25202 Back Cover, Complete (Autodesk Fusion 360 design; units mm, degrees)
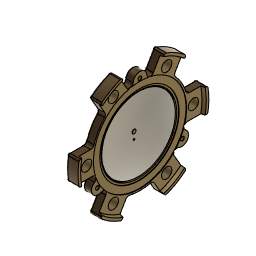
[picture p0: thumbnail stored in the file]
parameter "Diaphragm_Slot_Depth" = 0.508 comment "SWG 25"
parameter "Diaphragm_Tolerance" = 0.0992 (= "( 1 / 256 ) * 1 in")
parameter "Bolt_Holes_Tolerance" = 1.5875 (= "( 1 / 16 ) * 1 in")
parameter "Diaphragm_Ring_Slot_Depth" = 0.508 comment "SWG 25"
sketch "Main Profile" plane through (0, 0, 0) normal (0, 1, 0) x axis (1, 0, 0)
  line L1 (0, 42.8625) -> (0, -42.8625)
  line L2 (0, -44.45) -> (0, -42.8625)
  line L3 (114.3635, -44.45) -> (0, -44.45)
  line L4 (0, -50.8) -> (0, -44.45)
  line L5 (-25.4, 0) -> (0, 0)
  line L6 (17.4625, 0) -> (0, 0)
  line L7 (-7.9375, -44.45) -> (0, -44.45)
  line L8 (-7.9375, -34.5258) -> (-7.9375, -44.45)
  line L9 (-0.508, -42.8625) -> (0, -42.8625)
  line L10 (-0.508, -36.5125) -> (-0.508, -42.8625)
  line L11 (-1.016, -36.5125) -> (-0.508, -36.5125)
  line L12 (-1.016, -34.925) -> (-1.016, -36.5125)
  line L13 (-2.6035, -34.925) -> (-1.016, -34.925)
  line L14 (-2.6035, -32.3877) -> (-2.6035, -34.925)
  line L15 (-7.9375, -50.8) -> (0, -50.8)
  line L16 (-7.9375, -44.45) -> (-7.9375, -50.8)
  line L17 (-25.4, 0) -> (-20.6375, 0)
  line L18 (-6.35, 0) -> (-20.6375, 0)
  line L19 (-6.35, -1.5875) -> (-6.35, 0)
  line L20 (-6.35, -4.7625) -> (-6.35, -1.5875)
  line L21 (-25.3706, -1.5875) -> (-6.35, -1.5875)
  line L22 (-20.1046, -6.35) -> (-6.35, -4.7625)
  line L23 (-1.3921, -33.9302) -> (-2.16, -34.1313)
  line L24 (122.1287, -1.5875) -> (-1.3921, -33.9302)
  line L25 (-5.5562, 0) -> (-5.5562, -1.5875)
  line L26 (-5.5562, 0) -> (-6.35, 0)
  line L27 (-5.5562, -1.5875) -> (-6.35, -1.5875)
  line L28 (-4.7625, 0) -> (-5.5562, 0)
  line L29 (-19.05, -2.3812) -> (-19.05, -1.5875)
  line L30 (-25.3338, -2.3812) -> (-19.05, -2.3812)
  line L31 (-19.05, -6.2283) -> (-19.05, -2.3812)
  line L32 (-5.5561, -1.7859) -> (-5.4569, -1.7859)
  arc A1 centre (17.4625, 0) radius 42.8625 clockwise from (-7.9375, -34.5258) to (-25.4, 0)
  arc A2 centre (17.4625, 0) radius 38.1 clockwise from (-2.6035, -32.3877) to (-20.6375, 0)
  arc A3 centre (-16.2556, -9.1018) radius 3.175 clockwise from (-19.3209, -9.9293) to (-16.6197, -5.9478)
  arc A4 centre (122.1287, -1.5875) radius 128.4787 clockwise from (-2.16, -34.1313) to (-6.35, -1.5875)
  arc A5 centre (122.1287, -1.5875) radius 127.685 clockwise from (-1.3921, -33.9302) to (-5.5562, -1.5875)
  arc A6 centre (-7.4064, 0) radius 2.6439 clockwise from (-4.7625, 0) to (-5.4569, -1.7859)
  arc A7 centre (-46.7072, 0) radius 21.5057 clockwise from (-25.2016, 0) to (-25.3338, -2.3812)
  point P4 (0, 0)
  point P1 (0, 0)
  point P8 (0, 0)
  point P12 (0, 0)
  point P11 (17.4625, 0)
  point P13 (17.4625, 0)
  point P22 (-20.6375, 0)
  point P24 (-6.35, 0)
  point P27 (-25.3706, -1.5875)
  point P28 (-20.1046, -6.35)
  point P30 (-16.6197, -5.9478)
  point P29 (-19.3209, -9.9293)
  point P20 (-2.6035, -32.3877)
  point P33 (122.1287, -1.5875)
  point P35 (122.1287, -1.5875)
  point P38 (-5.5562, 0)
  point P39 (-4.7625, 0)
  point P40 (-19.05, -1.5875)
  point P42 (-25.3338, -2.3812)
  point P43 (-19.05, -6.2283)
  point P45 (-7.4064, 0)
  point P46 (-5.5561, -1.7859)
  point P47 (-25.2016, 0)
  point P48 (-46.7072, 0)
  point P5 (0, -44.45)
  point P2 (0, -42.8625)
  point P7 (0, -50.8)
  point P9 (-25.4, 0)
  point P14 (-7.9375, -44.45)
  point P15 (-0.508, -42.8625)
  point P16 (-0.508, -36.5125)
  point P17 (-1.016, -36.5125)
  point P18 (-1.016, -34.925)
  point P26 (-6.35, -4.7625)
  point P32 (-2.16, -34.1313)
  point P34 (-1.3921, -33.9302)
  point P44 (-5.4569, -1.7859)
  vertical L1
  midpoint L1 P4
  coincident P1 P4
  parallel L1 L2
  horizontal L3
  perpendicular L3 L4
  coincident P4 P8
  horizontal L5
  coincident P4 P12
  coincident P11 P13
  horizontal L6
  horizontal L7
  vertical L8
  perpendicular L1 L9
  perpendicular L9 L10
  perpendicular L10 L11
  perpendicular L11 L12
  perpendicular L12 L13
  perpendicular L13 L14
  perpendicular L4 L15
  vertical L16
  coincident L5 P22
  concentric A1 A2
  coincident L5 P24
  perpendicular L5 L19
  perpendicular L5 L20
  coincident A1 P27
  horizontal L21
  coincident A2 P28
  tangent L22 A3
  coincident L22 P30
  coincident A2 P29
  tangent A2 A3
  tangent L20 A4
  coincident P20 A4
  coincident P33 P35
  parallel L23 L24
  concentric A4 A5
  coincident L5 P38
  tangent A5 L25
  vertical L25
  coincident L5 P39
  perpendicular L25 L28
  coincident L21 P40
  perpendicular L21 L29
  coincident A1 P42
  perpendicular L29 L30
  coincident L22 P43
  perpendicular L30 L31
  coincident L5 P45
  coincident A5 P46
  horizontal L32
  coincident L5 P47
  coincident L17 P48
  dimension "d1" distance P1 P5 = 44.45 (= "1 3/4")
  dimension "d2" distance P2 P5 = 1.5875 (= "( 1 / 16 ) * 1 in")
  dimension "d4" distance P4 P7 = 50.8
  dimension "d6" radius A1 = 42.8625 (= "1 11/16")
  dimension "d7" distance P8 P9 = 25.4
  dimension "d8" distance P5 P14 = 7.9375 (= "( 5 / 16 ) * 1 in")
  dimension "d10" distance P2 P15 = 0.508 (= "Diaphragm_Ring_Slot_Depth")
  dimension "d11" distance P16 P17 = 0.508 (= "Diaphragm_Slot_Depth")
  dimension "d12" distance P15 P16 = 6.35 (= "( 1 / 4 ) * 1 in")
  dimension "d13" distance P17 P18 = 1.5875 (= "( 1 / 16 ) * 1 in")
  dimension "d14" distance A1 A2 = 4.7625 (= "( 3 / 16 ) * 1 in")
  dimension "d16" distance L18 L21 = 1.5875 (= "( 1 / 16 ) * 1 in")
  dimension "d17" distance L5 P26 = 4.7625 (= "( 3 / 16 ) * 1 in")
  dimension "d18" distance L5 P28 = 6.35 (= "( 1 / 4 ) * 1 in")
  dimension "d19" radius A3 = 3.175 (= "( 1 / 8 ) * 1 in")
  dimension "d20" distance P9 L20 = 19.05 (= "( 3 / 4 ) * 1 in")
  dimension "d56" distance P32 P34 = 0.7937 (= "( 1 / 32 ) * 1 in")
  dimension "d58" distance L6 P32 = 34.1313 (= "1 11/32")
  dimension "d67" distance P38 P39 = 0.7937 (= "( 1 / 32 ) * 1 in")
  dimension "d77" distance P9 L31 = 6.35 (= "( 1 / 4 ) * 1 in")
  dimension "d79" distance L5 L30 = 2.3813 (= "( 3 / 32 ) * 1 in")
  dimension "d80" distance P44 P46 = 0.0992 (= "( 1 / 256 ) * 1 in")
  dimension "d82" distance L27 L32 = 0.1984 (= "( 1 / 128 ) * 1 in")
  dimension "d83" distance P9 P47 = 0.1984 (= "( 1 / 128 ) * 1 in")
  dimension "d84" distance L12 L14 = 1.5875
  dimension "d3" Text1-Height = 6.35 (= "( 1 / 4 ) * 1 in")
  dimension "d5" Text2-Height = 6.35
revolve "Revolve1" sketch "Main Profile" AlongAngle 360
sketch "Flange Profile" plane through (0, 0, 0) normal (1, 0, 0) x axis (0, 1, 0)
  line L1 (0, 50.8) -> (0, 0)
  line L2 (60.325, 0) -> (0, 0)
  line L3 (60.325, -11.1125) -> (60.325, 11.1125)
  line L4 (43.0385, 11.1125) -> (60.325, 11.1125)
  line L5 (43.0385, -11.1125) -> (60.325, -11.1125)
  line L6 (39.7862, 46.6867) -> (20.5388, 57.7992)
  line L7 (11.8956, 42.8287) -> (20.5388, 57.7992)
  line L8 (31.143, 31.7162) -> (39.7862, 46.6867)
  line L9 (30.1625, 52.243) -> (0, 0)
  line L10 (-20.5388, 57.7992) -> (-39.7862, 46.6867)
  line L11 (-31.143, 31.7162) -> (-39.7862, 46.6867)
  line L12 (-11.8956, 42.8287) -> (-20.5388, 57.7992)
  line L13 (-30.1625, 52.243) -> (0, 0)
  line L14 (-60.325, 11.1125) -> (-60.325, -11.1125)
  line L15 (-43.0385, -11.1125) -> (-60.325, -11.1125)
  line L16 (-43.0385, 11.1125) -> (-60.325, 11.1125)
  line L17 (-60.325, 0) -> (0, 0)
  line L18 (-39.7862, -46.6867) -> (-20.5388, -57.7992)
  line L19 (-11.8956, -42.8287) -> (-20.5388, -57.7992)
  line L20 (-31.143, -31.7162) -> (-39.7862, -46.6867)
  line L21 (-30.1625, -52.243) -> (0, 0)
  line L22 (20.5388, -57.7992) -> (39.7862, -46.6867)
  line L23 (31.143, -31.7162) -> (39.7862, -46.6867)
  line L24 (11.8956, -42.8287) -> (20.5388, -57.7992)
  line L25 (30.1625, -52.243) -> (0, 0)
  line L26 (-43.9941, -25.4) -> (0, 0)
  line L27 (43.9941, -25.4) -> (0, 0)
  circle C1 centre (0, 0) radius 42.8625
  circle C2 centre (0, 0) radius 44.45
  circle C3 centre (0, 45.2437) radius 1.5875
  arc A1 centre (0, 44.45) radius 6.35 clockwise from (-6.3375, 44.8477) to (6.3375, 44.8477)
  circle C4 centre (0, 0) radius 32.3877
  circle C5 centre (0, 0) radius 34.925
  circle C6 centre (0, 0) radius 34.925
  circle C7 centre (0, 0) radius 36.5125
  circle C8 centre (0, 0) radius 36.5125
  circle C9 centre (0, 0) radius 42.8625
  circle C10 centre (49.2125, 0) radius 4.7625
  circle C11 centre (0, 0) radius 60.325
  circle C12 centre (0, 0) radius 57.15
  circle C13 centre (24.6063, 42.6193) radius 4.7625
  circle C14 centre (-24.6062, 42.6193) radius 4.7625
  circle C15 centre (-49.2125, 0) radius 4.7625
  circle C16 centre (-24.6063, -42.6193) radius 4.7625
  circle C17 centre (24.6062, -42.6193) radius 4.7625
  arc A2 centre (9.508, 45.0467) radius 3.1767 clockwise from (12.2591, 43.4584) to (6.3375, 44.8477)
  arc A3 centre (-9.508, 45.0467) radius 3.1767 clockwise from (-6.3375, 44.8477) to (-12.2591, 43.4584)
  arc A4 centre (-34.2576, -30.7575) radius 3.1767 clockwise from (-35.6705, -27.9123) to (-31.5065, -32.3459)
  arc A5 centre (-38.4948, -22.225) radius 6.35 clockwise from (-35.6705, -27.9123) to (-42.008, -16.9354)
  arc A6 centre (-43.7656, -14.2892) radius 3.1767 clockwise from (-43.7656, -11.1125) to (-42.008, -16.9354)
  circle C18 centre (-39.1822, -22.6219) radius 1.5875
  arc A7 centre (43.7656, -14.2892) radius 3.1767 clockwise from (42.008, -16.9354) to (43.7656, -11.1125)
  arc A8 centre (38.4948, -22.225) radius 6.35 clockwise from (42.008, -16.9354) to (35.6705, -27.9123)
  arc A9 centre (34.2576, -30.7575) radius 3.1767 clockwise from (31.5065, -32.3459) to (35.6705, -27.9123)
  circle C19 centre (39.1822, -22.6219) radius 1.5875
  point P1 (0, 0)
  point P3 (0, 0)
  point P4 (0, 50.8)
  point P9 (0, 44.45)
  point P10 (0, 0)
  point P14 (60.325, 0)
  point P11 (60.325, 0)
  point P18 (43.0385, 11.1125)
  point P19 (43.0385, -11.1125)
  point P20 (49.2125, 0)
  point P58 (12.2591, 43.4584)
  point P60 (-12.2591, 43.4584)
  point P6 (0, 45.2437)
  point P12 (60.325, 11.1125)
  point P13 (60.325, -11.1125)
  point P28 (0, 0)
  coincident P1 P3
  vertical L1
  coincident P4 A1
  coincident L1 P9
  coincident P1 P10
  perpendicular L1 L2
  vertical L3
  midpoint L3 P14
  coincident P11 P14
  coincident C2 P18
  perpendicular L3 L4
  coincident C2 P19
  perpendicular L3 L5
  coincident L2 P20
  concentric C4 C11
  coincident P14 C11
  concentric C6 C12
  coincident L7 P58
  tangent A1 A2
  tangent L7 A2
  tangent A1 A3
  tangent L12 A3
  coincident L12 P60
  tangent C1 A2
  tangent C9 A3
  coincident L1 P6
  dimension "d22" distance P3 P4 = 50.8
  dimension "d23" diameter C3 = 3.175 (= "( 1 / 8 ) * 1 in")
  dimension "d25" distance P10 P11 = 60.325
  dimension "d26" distance P12 P13 = 22.225 (= "( 7 / 8 ) * 1 in")
  dimension "d27" diameter C10 = 9.525 (= "( 5 / 16 ) * 1 in + Bolt_Holes_Tolerance")
  dimension "d28" distance P1 P20 = 49.2125 (= "1 15/16")
  dimension "d29" distance C11 C12 = 3.175 (= "( 1 / 8 ) * 1 in")
  dimension "d33" radius A1 = 6.35 (= "( 1 / 4 ) * 1 in")
  dimension "d50" distance P6 P28 = 45.2437 (= "1 25/32")
  dimension "d31" C-Pattern1-Angle = 360
  dimension "d35" C-Pattern2-Angle = 360
extrude "Extrude1" add sketch "Flange Profile" profile of C2 C3 A1 L4 L5 C10 C11 C12 L7 L8 C13 L11 L12 C14 L15 L16 C15 L19 L20 C16 L23 L24 C17 A2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 against normal blind 7.9375 (magnitude of "( -5 / 16 ) * 1 in")
extrude "Extrude2" cut sketch "Flange Profile" profile of C1 C2 C9 A2 A3 A4 A6 A7 A9 against normal blind 7.9375 (magnitude of "( -5 / 16 ) * 1 in")
extrude "Extrude3" add sketch "Flange Profile" profile of L4 L5 C11 C12 L7 L8 L11 L12 L15 L16 L19 L20 L23 L24 along normal blind 3.175 (= "( 1 / 8 ) * 1 in")
fillet "Fillet1" radius 3.175 (= "( 1 / 8 ) * 1 in")
fillet "Fillet2" radius 6.35 (= "( 1 / 4 ) * 1 in")
extrude "Extrude4" cut sketch "Flange Profile" profile of C2 C3 C18 C19 against normal blind 7.9375 (magnitude of "( -5 / 16 ) * 1 in")
chamfer "Chamfer1" distance 0.1984 (= "( 1 / 128 ) * 1 in")
chamfer "Chamfer2" sketch "Flange Profile" distance 0.7937 (= "( 1 / 32 ) * 1 in") distance 3.175 (= "( 1 / 8 ) * 1 in")
fillet "Fillet3" radius 1.5875 (= "( 1 / 16 ) * 1 in")
revolve "Revolve2" sketch "Main Profile" AlongAngle 360 bodies "Chamber Plate (Installed)"
offset_faces "OffsetFaces1"
sketch "Diaphragm Tolerance Profile" plane through (0, 0, 0) normal (1, 0, 0) x axis (0, 1, 0)
  line L1 (45.4314, 11.1125) -> (56.0592, 11.1125)
  line L2 (37.6533, 42.9924) -> (32.3394, 33.7885)
  line L3 (12.2591, 43.4584) -> (18.4059, 54.1049)
  line L4 (56.0592, -11.1125) -> (43.7656, -11.1125)
  line L5 (42.9617, 0) -> (0, 0)
  arc A1 centre (0, 0) radius 57.15 clockwise from (56.0592, 11.1125) to (56.0592, -11.1125)
  arc A2 centre (45.4314, 14.2875) radius 3.175 clockwise from (45.4314, 11.1125) to (42.4026, 13.335)
  arc A3 centre (0, 0) radius 44.45 clockwise from (32.7497, 30.0542) to (42.4026, 13.335)
  arc A4 centre (35.089, 32.201) radius 3.175 clockwise from (32.7497, 30.0542) to (32.3394, 33.7885)
  arc A5 centre (0, 0) radius 57.15 clockwise from (18.4059, 54.1049) to (37.6533, 42.9924)
  arc A6 centre (9.508, 45.0467) radius 3.1767 clockwise from (12.2591, 43.4584) to (8.8519, 41.9385)
  arc A7 centre (0, 0) radius 42.8625 clockwise from (8.8519, 41.9385) to (40.7458, -13.3032)
  arc A8 centre (43.7656, -14.2892) radius 3.1767 clockwise from (40.7458, -13.3032) to (43.7656, -11.1125)
  circle C1 centre (24.6063, 42.6193) radius 4.7625
  circle C2 centre (49.2125, 0) radius 4.7625
  circle C3 centre (0, 0) radius 42.9617
  circle C4 centre (0, 0) radius 42.8625
  point P1 (0, 0)
  point P21 (0, 0)
  point P22 (0, 0)
  point P23 (0, 0)
  point P24 (42.9617, 0)
  point P25 (42.8625, 0)
  coincident P1 P21
  coincident P1 P22
  coincident P21 P23
  coincident C3 P24
  horizontal L5
  coincident C4 P25
  coincident L5 P25
  dimension "d62" distance A7 C3 = 0.0992 (= "Diaphragm_Tolerance")
  dimension "d63" distance P24 P25 = 0.0992 (= "Diaphragm_Tolerance")
extrude "Extrude5" cut sketch "Diaphragm Tolerance Profile" profile of A6 A7 A8 C3 C4 no distance stored
revolve "Revolve3" sketch "Main Profile" AlongAngle 360 bodies "Chamber Plate Rivet"
sketch "Chamber Plate Hole Profile 1" plane through (-1.016, 0, 0) normal (1, 0, 0) x axis (0, 1, 0)
  line L1 (0, -6.35) -> (0, 0)
  circle C1 centre (0, 0) radius 34.925
  circle C2 centre (0, 0) radius 36.6117
  circle C3 centre (0, -6.35) radius 0.7938
  point P1 (0, 0)
  point P3 (0, 0)
  point P4 (0, -6.35)
  point P5 (0, -6.35)
  coincident P1 P3
  vertical L1
  coincident P4 P5
  dimension "d72" distance P3 P4 = 6.35 (= "( 1 / 4 ) * 1 in")
  dimension "d73" diameter C3 = 1.5875 (= "( 1 / 16 ) * 1 in")
extrude "Extrude6" cut sketch "Chamber Plate Hole Profile 1" profile of C3 against normal blind 6.35
sketch "Chamber Plate Profile 1" plane through (0, 0, 0) normal (0, 1, 0) x axis (1, 0, 0)
  line L1 (122.1287, -1.5875) -> (-1.3921, -33.9302)
  line L2 (-1.3921, -33.9302) -> (-2.16, -34.1313)
  line L3 (-5.5562, 0) -> (-5.5562, -1.5875)
  line L4 (-6.35, -1.5875) -> (-6.35, 0)
  line L5 (-5.5562, 0) -> (-6.35, 0)
  line L6 (-5.5562, -34.4663) -> (-5.5562, 0)
  line L7 (-6.35, -34.4663) -> (-5.5562, -34.4663)
  line L8 (-6.35, 0) -> (-6.35, -34.4663)
  line L9 (-6.35, -34.5281) -> (-5.5562, -34.5281)
  line L10 (-5.5562, -34.4663) -> (-5.5562, -34.5281)
  line L11 (-6.35, -34.4663) -> (-6.35, -34.5281)
  arc A1 centre (122.1287, -1.5875) radius 127.685 clockwise from (-1.3921, -33.9302) to (-5.5562, -1.5875)
  arc A2 centre (122.1287, -1.5875) radius 128.4787 clockwise from (-2.16, -34.1313) to (-6.35, -1.5875)
  arc A3 centre (-5.5562, -18.027) radius 16.4394 clockwise from (-1.3921, -33.9302) to (-5.5562, -34.4663)
  point P14 (-6.35, 0)
  point P16 (-6.35, 0)
  point P13 (-5.5562, 0)
  point P17 (-5.5562, 0)
  point P18 (-5.5562, 0)
  point P19 (-6.35, 0)
  point P5 (-1.3921, -33.9302)
  point P22 (-1.3921, -33.9302)
  point P24 (-5.5562, -34.5281)
  point P25 (-6.35, -34.5281)
  coincident P14 P16
  coincident P13 P17
  perpendicular L6 L7
  vertical L8
  coincident P17 P18
  vertical L6
  coincident P16 P19
  tangent L7 A3
  coincident P5 P22
  tangent L1 A3
  coincident L6 P24
  coincident L8 P25
  perpendicular L8 L9
  dimension "d90" distance P17 L9 = 34.5281 (= "1 23/64")
revolve "Revolve4" sketch "Chamber Plate Profile 1" AlongAngle 360 bodies "Chamber Plate (Uninstalled)"
sketch "Chamber Plate Hole Profile 2" plane through (-5.5562, 0, 0) normal (1, 0, 0) x axis (0, 1, 0)
  line L1 (0, -6.35) -> (0, 0)
  circle C1 centre (0, 0) radius 34.5281
  circle C2 centre (0, 0) radius 1.5875
  circle C3 centre (0, -6.35) radius 0.7937
  point P1 (0, 0)
  point P3 (0, 0)
  point P4 (0, 0)
  point P5 (0, -6.35)
  point P6 (0, -6.35)
  coincident P1 P3
  coincident P1 P4
  vertical L1
  coincident P5 P6
  dimension "d91" diameter C2 = 3.175 (= "( 1 / 8 ) * 1 in")
  dimension "d92" diameter C3 = 1.5875 (= "( 1 / 16 ) * 1 in")
  dimension "d93" distance P4 P5 = 6.35 (= "( 1 / 4 ) * 1 in")
extrude "Extrude7" cut sketch "Chamber Plate Hole Profile 2" profile of C2 C3 against normal blind 0.7937 (magnitude of "( -1 / 32 ) * 1 in")
named bodies: "Back Cover", "Chamber Plate (Installed)", "Chamber Plate Rivet", "Chamber Plate (Uninstalled)"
